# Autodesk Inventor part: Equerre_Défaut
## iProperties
Shininess: 64.0
Length Units: 11269
Angle Units: 11279
Time Units: 11290
Mass Units: 11283
Length Display Precision: 3
Angle Display Precision: 2
Compacted: True
Part Number: Equerre_Défaut
Document SubType Name: Modeling
Created: 2006-11
Material: Par défaut
Designer: profs_sti
Density: 0.0
Volumn: 0.0
Area: 0.0
PropertySet Name: Model Information
Control State: 0
Master: False
Checked Out: False
Author: profs_sti
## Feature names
1. Base1
